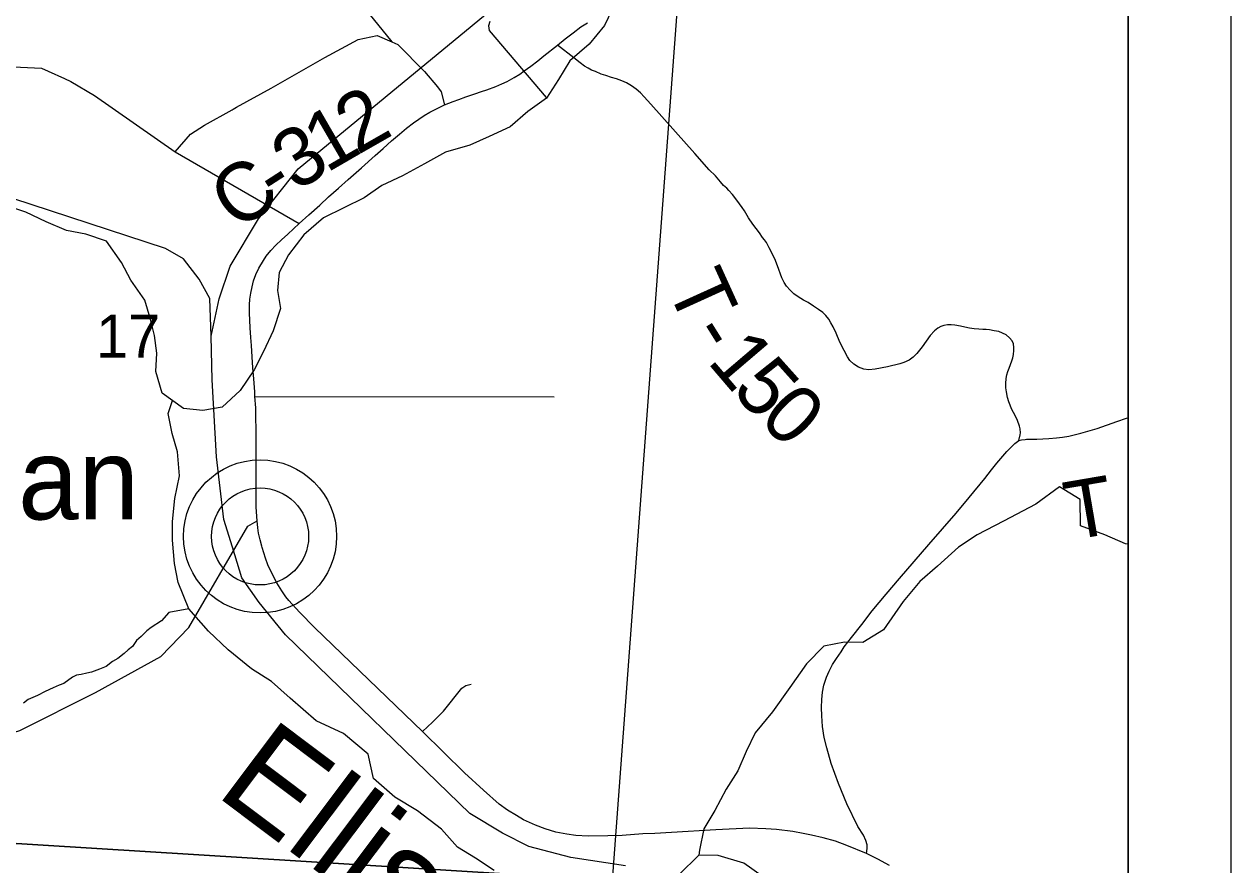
# Model space of a CAD drawing. Extents: x 0 to 34, y 0 to 22.
# Drawn here: x 7.827 to 9, y 17.328 to 18.145 of the extents above; entities that cross this region are included whole.
import ezdxf

# ---------------------------------------------------------------- set-up
doc = ezdxf.new("R2010")
doc.units = 0
for name, color, linetype in [('GM_X_County_Road', 7, 'Continuous'), ('GM_X_County_Road_Text', 7, 'Continuous'), ('GM_X_Minor_River', 7, 'Continuous'), ('GM_X_Minor_River_Text', 7, 'Continuous'), ('GM_X_Rail_Line', 7, 'Continuous'), ('GM_X_Section', 7, 'Continuous'), ('GM_X_Section_Text', 7, 'Continuous'), ('GM_X_State_Route', 7, 'Continuous'), ('GM_X_Township_Road', 7, 'Continuous'), ('GM_X_Township_Road_Text', 7, 'Continuous'), ('GM_X_Unincorporated', 7, 'Continuous'), ('GM_X_Unincorporated_Location', 7, 'Continuous'), ('GM_X_Unincorporated_Text', 7, 'Continuous'), ('SH_Cut_Line', 7, 'Continuous'), ('SH_Data', 7, 'Continuous')]:
    doc.layers.add(name, color=color, linetype=linetype)

msp = doc.modelspace()

# ---------------------------------------------------------------- linework, layer by layer
at = {"layer": 'GM_X_County_Road'}
for points in [[(8.0289, 18.0619), (8.0298, 18.0624), (8.0333, 18.0644), (8.0669, 18.0831), (8.1191, 18.1129), (8.1514, 18.1303), (8.17, 18.1341), (8.1841, 18.1279), (8.1899, 18.1254), (8.2161, 18.0993), (8.2285, 18.0843), (8.2322, 18.0794), (8.2354, 18.0667)], [(7.9734, 18.0211), (7.9886, 18.0383), (8.0022, 18.047), (8.0289, 18.0619)], [(7.6306, 17.424), (7.672, 17.4307), (7.7035, 17.4327), (7.7327, 17.4304), (7.8225, 17.4585), (7.896, 17.4953), (7.9597, 17.5306), (7.9869, 17.5587), (8.0441, 17.6573), (8.0533, 17.6625)]]:
    msp.add_lwpolyline(points, dxfattribs=at)
at = {"layer": 'GM_X_Minor_River'}
for points in [[(8.4017, 18.1663), (8.3909, 18.1439), (8.376, 18.1258), (8.3573, 18.1095), (8.3462, 18.0914), (8.3347, 18.0732), (8.3164, 18.0604), (8.2992, 18.0453), (8.2787, 18.0359), (8.2601, 18.0277), (8.2365, 18.0206), (8.216, 18.0093), (8.1946, 17.9976), (8.1745, 17.9882), (8.1573, 17.9765), (8.1178, 17.957), (8.0987, 17.9404), (8.0838, 17.9211), (8.0746, 17.9037), (8.0729, 17.8862), (8.0758, 17.8687), (8.0689, 17.8471), (8.0593, 17.8271), (8.0504, 17.8093), (8.0366, 17.7892), (8.0191, 17.773), (8.0005, 17.7696), (7.9815, 17.7716), (7.9608, 17.7866), (7.9548, 17.8075), (7.9557, 17.8253), (7.9535, 17.8424)], [(8.2794, 18.1478), (8.2782, 18.1436), (8.2789, 18.1391), (8.3342, 18.0738)], [(7.9535, 17.8424), (7.9491, 17.8595), (7.9439, 17.877), (7.9304, 17.8964), (7.9214, 17.9136), (7.9068, 17.9341), (7.8867, 17.9411), (7.8678, 17.9446), (7.8481, 17.9531), (7.8284, 17.9623), (7.811, 17.9684)], [(8.2838, 17.3224), (8.2657, 17.3343), (8.2479, 17.345), (8.2325, 17.3626), (8.2091, 17.3805), (8.1872, 17.3936), (8.1664, 17.4119), (8.1613, 17.4355), (8.1372, 17.4557), (8.1107, 17.468), (8.0854, 17.4898), (8.0673, 17.5062), (8.0477, 17.5184), (8.0251, 17.5371), (8.0059, 17.5551), (7.9867, 17.5768), (7.9766, 17.6023), (7.9729, 17.6209), (7.9708, 17.6437), (7.9709, 17.6616), (7.9733, 17.684), (7.9777, 17.706), (7.9759, 17.7295), (7.9707, 17.7474), (7.9667, 17.7668), (7.9709, 17.7792)], [(8.9, 17.6397), (8.8976, 17.6401), (8.8776, 17.6489), (8.8537, 17.6574), (8.8535, 17.6832), (8.8335, 17.6955), (8.8103, 17.6785), (8.779, 17.662), (8.7532, 17.6488), (8.7353, 17.6368), (8.7147, 17.6183), (8.6975, 17.6035), (8.6814, 17.5839), (8.6623, 17.5563), (8.6421, 17.5442), (8.6243, 17.5443), (8.6042, 17.5406), (8.5874, 17.5232), (8.5713, 17.5002), (8.5544, 17.4767), (8.5376, 17.4563), (8.5288, 17.4381), (8.5207, 17.4192), (8.5092, 17.4014), (8.4984, 17.3809), (8.4877, 17.3628), (8.4834, 17.3423), (8.4826, 17.3374)], [(7.9867, 17.5768), (7.9674, 17.5731), (7.9604, 17.5652), (7.9501, 17.5588), (7.9459, 17.5555), (7.9405, 17.5498), (7.9359, 17.5461), (7.9321, 17.5401), (7.9279, 17.5371), (7.924, 17.5333), (7.9179, 17.5285), (7.9125, 17.5255), (7.9064, 17.5206), (7.8999, 17.5181), (7.8923, 17.5151), (7.8878, 17.5144), (7.8821, 17.513), (7.8775, 17.5123), (7.8737, 17.5104), (7.8653, 17.5041), (7.8607, 17.5026), (7.855, 17.5), (7.847, 17.4963), (7.8397, 17.4926), (7.8306, 17.4885), (7.826, 17.4852)], [(8.5443, 17.3169), (8.5265, 17.3295), (8.5016, 17.3369), (8.4826, 17.3374), (8.4635, 17.3185)]]:
    msp.add_lwpolyline(points, dxfattribs=at)
at = {"layer": 'GM_X_Rail_Line'}
for points in [[(8.0084, 17.842), (8.0162, 17.8783), (8.0271, 17.9099), (8.0546, 17.9559), (8.0931, 18.0044), (8.4314, 18.2836), (8.5429, 18.3703), (8.7331, 18.5379), (8.8556, 18.668), (8.9, 18.713)], [(8.0084, 17.842), (8.0071, 17.8786), (7.997, 17.8973), (7.9816, 17.917), (7.9641, 17.927), (7.6293, 18.0366), (7.4337, 18.1028), (7.3817, 18.121), (7.3462, 18.1309), (7.3036, 18.1327), (7.2652, 18.1234), (7.2362, 18.1066), (7.1873, 18.0836), (6.9922, 17.9653), (6.9911, 17.9641), (6.4682, 17.6519)], [(8.4114, 17.3271), (8.3583, 17.3351), (8.3173, 17.3456), (8.2918, 17.3587), (8.2602, 17.3777), (8.0808, 17.5515), (8.0551, 17.5829), (8.0382, 17.607), (8.0294, 17.6367), (8.0207, 17.6635), (8.0136, 17.7246), (8.0094, 17.7994), (8.0084, 17.842)]]:
    msp.add_lwpolyline(points, dxfattribs=at)
at = {"layer": 'GM_X_Section'}
for points in [[(7.4583, 18.399), (8.4739, 18.3269), (8.3983, 17.3128), (7.3907, 17.3751)], [(7.3907, 17.3751), (8.3983, 17.3128), (8.3308, 16.3019), (7.3221, 16.3607)]]:
    msp.add_lwpolyline(points, close=True, dxfattribs=at)
at = {"layer": 'GM_X_State_Route'}
for points in [[(8.0941, 17.9514), (8.1035, 17.9597), (8.1141, 17.9693), (8.1227, 17.9772), (8.1274, 17.9814), (8.1324, 17.9859), (8.1417, 17.9942), (8.1547, 18.0056), (8.168, 18.0176), (8.1757, 18.0242), (8.1839, 18.0317), (8.1917, 18.0383), (8.1985, 18.0441), (8.2052, 18.0492), (8.2106, 18.0529), (8.2158, 18.0564), (8.2212, 18.0595), (8.2271, 18.0625), (8.2354, 18.0667), (8.2437, 18.07), (8.2492, 18.072), (8.2563, 18.0745), (8.265, 18.0775), (8.2713, 18.0797), (8.2765, 18.0814), (8.2854, 18.0846), (8.2911, 18.0871), (8.2962, 18.0895), (8.303, 18.0932), (8.3088, 18.0967), (8.3128, 18.0999), (8.3192, 18.1045), (8.3263, 18.1096), (8.332, 18.1145), (8.3452, 18.1249), (8.3529, 18.1308), (8.3604, 18.1367), (8.3679, 18.1426), (8.3746, 18.1466)], [(7.8097, 18.1042), (7.8437, 18.1024), (7.8499, 18.0996), (7.8658, 18.0924)], [(7.8658, 18.0924), (7.872, 18.0896), (7.895, 18.0757), (7.9734, 18.0211), (8.0941, 17.9514)], [(8.0533, 17.6625), (8.0523, 17.6757), (8.0522, 17.6843), (8.0524, 17.6905), (8.0523, 17.7063), (8.0523, 17.7228), (8.0523, 17.738), (8.0523, 17.7527), (8.0521, 17.7611), (8.0519, 17.7722), (8.0511, 17.7832), (8.0509, 17.7878), (8.05, 17.8004), (8.0492, 17.8112), (8.0485, 17.8218), (8.0477, 17.8327), (8.0472, 17.8405), (8.0466, 17.8499), (8.0461, 17.8573), (8.0458, 17.8642), (8.0459, 17.8724), (8.0463, 17.878), (8.0471, 17.8837), (8.0484, 17.8898), (8.0498, 17.8957), (8.0521, 17.9018), (8.055, 17.9081), (8.0593, 17.9153), (8.0621, 17.9196), (8.0666, 17.925), (8.0715, 17.9303), (8.0769, 17.9354), (8.0832, 17.9412), (8.0941, 17.9514)], [(8.0577, 17.6376), (8.0561, 17.6439), (8.0546, 17.6504), (8.0539, 17.6557), (8.0533, 17.6625)], [(8.6682, 17.3274), (8.6569, 17.3335), (8.6458, 17.3389), (8.6267, 17.3467), (8.6155, 17.3508), (8.6035, 17.3543), (8.5924, 17.3569), (8.5841, 17.3585), (8.574, 17.3603), (8.5581, 17.3622), (8.5477, 17.3629), (8.5319, 17.3636), (8.4991, 17.3619), (8.456, 17.3595), (8.44, 17.3585), (8.4284, 17.358), (8.4082, 17.3566), (8.3942, 17.356), (8.375, 17.3558), (8.3631, 17.3565), (8.3542, 17.3578), (8.3438, 17.3598), (8.3334, 17.3628), (8.3239, 17.3664), (8.3123, 17.3716), (8.3053, 17.3758), (8.2966, 17.381), (8.2885, 17.3868), (8.2732, 17.4004), (8.2548, 17.4174), (8.2141, 17.4576), (8.1094, 17.5582), (8.0943, 17.5736), (8.0839, 17.585), (8.0812, 17.5884), (8.0773, 17.5943), (8.0723, 17.602), (8.0703, 17.6058), (8.0637, 17.6196), (8.0613, 17.6261), (8.058, 17.6363), (8.0577, 17.6376)]]:
    msp.add_lwpolyline(points, dxfattribs=at)
at = {"layer": 'GM_X_Township_Road'}
for p, q in [((8.1154, 18.2136), (8.1841, 18.1279)), ((8.0511, 17.7832), (8.3419, 17.7828))]:
    msp.add_line(p, q, dxfattribs=at)
for points in [[(8.7939, 17.7404), (8.795, 17.7461), (8.7953, 17.748), (8.7951, 17.7517), (8.7944, 17.7544), (8.7927, 17.7599), (8.7902, 17.7648), (8.7871, 17.7706), (8.7841, 17.778), (8.7827, 17.7821), (8.7817, 17.7877), (8.7812, 17.7918), (8.7812, 17.796), (8.7816, 17.8006), (8.7822, 17.8042), (8.7833, 17.8075), (8.7846, 17.8108), (8.7859, 17.8143), (8.787, 17.8178), (8.788, 17.8209), (8.7886, 17.8242), (8.7891, 17.8281), (8.7891, 17.8309), (8.7886, 17.8343), (8.7873, 17.8373), (8.7848, 17.8403), (8.7816, 17.8433), (8.7781, 17.8448), (8.7745, 17.8463), (8.7697, 17.8472), (8.7654, 17.8479), (8.762, 17.8482), (8.7588, 17.8484), (8.7549, 17.8488), (8.7505, 17.8491), (8.7459, 17.8498), (8.7414, 17.8506), (8.7371, 17.8515), (8.7316, 17.8526), (8.7279, 17.853), (8.7246, 17.853), (8.7208, 17.8522), (8.7179, 17.8513), (8.7151, 17.8497), (8.7117, 17.8471), (8.7076, 17.8424), (8.7, 17.8314), (8.6947, 17.8251), (8.691, 17.8216), (8.6871, 17.8186), (8.6819, 17.8164), (8.678, 17.8151), (8.6662, 17.8122), (8.654, 17.8098), (8.6481, 17.8091), (8.6432, 17.8099), (8.638, 17.8119), (8.6333, 17.8145), (8.6296, 17.8183), (8.6274, 17.8217), (8.6239, 17.828), (8.6198, 17.8362), (8.6162, 17.8447), (8.6132, 17.8508), (8.6112, 17.8548), (8.6091, 17.8585), (8.6062, 17.8621), (8.6032, 17.8649), (8.5991, 17.8678), (8.5942, 17.871), (8.5889, 17.8747), (8.5846, 17.877), (8.5793, 17.8802), (8.575, 17.8831), (8.5716, 17.8866), (8.5681, 17.8904), (8.5657, 17.8941), (8.5635, 17.8987), (8.5591, 17.9103), (8.5565, 17.9172), (8.5511, 17.9277), (8.5486, 17.9328), (8.5467, 17.9356), (8.5446, 17.9377), (8.5417, 17.9423), (8.5353, 17.9509), (8.5311, 17.9568), (8.527, 17.9637), (8.5249, 17.967), (8.5198, 17.9741), (8.5153, 17.9797), (8.512, 17.9835), (8.5098, 17.9858), (8.5066, 17.9885), (8.5037, 17.992), (8.499, 17.9976), (8.4929, 18.0037), (8.4787, 18.0196), (8.4601, 18.0406), (8.436, 18.0673), (8.4296, 18.0746), (8.426, 18.0785), (8.4219, 18.0821), (8.4173, 18.0853), (8.4125, 18.088), (8.4077, 18.0901), (8.4026, 18.0919), (8.3977, 18.0934), (8.3924, 18.0952), (8.3879, 18.0967), (8.3822, 18.0991), (8.3785, 18.1006), (8.3752, 18.1024), (8.3714, 18.1045), (8.3673, 18.1075), (8.3611, 18.1126), (8.3452, 18.1249)], [(8.7939, 17.7404), (8.7965, 17.7411), (8.8001, 17.7415), (8.8014, 17.7416), (8.8064, 17.7416), (8.8112, 17.7416), (8.8231, 17.7424), (8.8306, 17.7429), (8.8364, 17.7436), (8.8423, 17.7448), (8.8488, 17.7464), (8.854, 17.7477), (8.8608, 17.7496), (8.87, 17.7522), (8.8891, 17.7588), (8.8986, 17.7621), (8.9, 17.7625)], [(8.7673, 17.7118), (8.7726, 17.7184), (8.7823, 17.7297), (8.7853, 17.733), (8.79, 17.7375), (8.7939, 17.7404)], [(8.6458, 17.3389), (8.6465, 17.3437), (8.6464, 17.3473), (8.6452, 17.3515), (8.6427, 17.3568), (8.6374, 17.3653), (8.6267, 17.3871), (8.6184, 17.4069), (8.6114, 17.4264), (8.607, 17.4416), (8.6046, 17.4518), (8.6031, 17.4624), (8.6022, 17.4727), (8.6021, 17.4809), (8.6023, 17.4885), (8.603, 17.4959), (8.6044, 17.5026), (8.6068, 17.5103), (8.6094, 17.5163), (8.6128, 17.5228), (8.6166, 17.5285), (8.621, 17.535), (8.6239, 17.5397), (8.6311, 17.5488), (8.6411, 17.5615), (8.6511, 17.575), (8.6648, 17.591), (8.6777, 17.6063), (8.7064, 17.6392), (8.7328, 17.6699), (8.7455, 17.6851), (8.7609, 17.7036), (8.7673, 17.7118)], [(8.2141, 17.4576), (8.2236, 17.4666), (8.2345, 17.4772), (8.2524, 17.4998), (8.256, 17.5023), (8.2613, 17.5035)]]:
    msp.add_lwpolyline(points, dxfattribs=at)
at = {"layer": 'GM_X_Township_Road_Text'}
msp.add_lwpolyline([(8.9, 17.2802), (8.9, 18.2954), (8.4739, 18.3269), (8.3983, 17.3128)], close=True, dxfattribs=at)
at = {"layer": 'GM_X_Unincorporated'}
msp.add_lwpolyline([(8.9, 14.2264), (8.9, 20.3234), (8.6245, 20.3436), (7.6038, 20.4229), (7.3955, 20.4364), (6.962, 20.4644), (6.8381, 20.4724), (6.7584, 20.4776), (6.6718, 20.4832), (6.6484, 20.4847), (4.3099, 20.6409), (3.8602, 20.6728), (3.5651, 20.6937), (3.5462, 20.4144), (3.5457, 20.4056), (3.5456, 20.4047), (3.5099, 19.8769)], dxfattribs=at)
for radius in [0.0744, 0.0472]:
    msp.add_circle((8.0561, 17.6472), radius, dxfattribs=at)
at = {"layer": 'GM_X_Unincorporated_Location'}
msp.add_line((8.0561, 17.6472), (8.0561, 17.6472), dxfattribs=at)
at = {"layer": 'SH_Cut_Line'}
msp.add_lwpolyline([(8.9, 14.1), (8.9, 20.9), (6.769, 20.9), (6.6568, 20.5136), (6.6484, 20.4847), (4.3099, 20.6409), (3.8602, 20.6728), (3.5651, 20.6937), (3.5462, 20.4144), (3.5457, 20.4056), (3.5456, 20.4047), (3.5099, 19.8769), (3.4599, 19.1361), (3.4595, 19.1305), (3.4011, 18.2653), (3.709, 17.484), (3.7367, 17.4136), (3.972, 16.8916), (4.0882, 16.6114), (4.2937, 16.1161)], dxfattribs=at)
at = {"layer": 'SH_Data'}
for p, q in [((9, 21), (9, 14)), ((8.9, 20.9), (8.9, 14.1))]:
    msp.add_line(p, q, dxfattribs=at)

# ---------------------------------------------------------------- texts
at = {"layer": 'GM_X_County_Road_Text'}
for s, rotation, p in [('2', 29.7271, (8.1506, 18.0175)), ('1', 30.1118, (8.1204, 18)), ('3', 31.4841, (8.0908, 17.9819)), ('C', 35.3335, (8.034, 17.9429)), ('-', 32.7981, (8.0715, 17.9695))]:
    msp.add_text(s, height=0.0568, rotation=rotation, dxfattribs=at).set_placement(p)
at = {"layer": 'GM_X_Minor_River_Text'}
msp.add_text('Ellisonville', height=0.094688, rotation=323.0648, dxfattribs=at).set_placement((8.0111, 17.3967))
at = {"layer": 'GM_X_Section_Text'}
msp.add_text('17', height=0.04186, rotation=0, dxfattribs=at).set_placement((7.8966, 17.821))
at = {"layer": 'GM_X_Township_Road_Text'}
for s, rotation, p in [('T', 294.4333, (8.4508, 17.8901)), ('-', 301.9874, (8.4723, 17.8442)), ('1', 310.4588, (8.49, 17.817)), ('5', 311.8019, (8.5137, 17.7893)), ('0', 315.4946, (8.5398, 17.7603)), ('T', 9.7195, (8.8438, 17.6432))]:
    msp.add_text(s, height=0.0568, rotation=rotation, dxfattribs=at).set_placement(p)
at = {"layer": 'GM_X_Unincorporated_Text'}
msp.add_text('Lisman', height=0.07898, rotation=0, dxfattribs=at).set_placement((7.5979, 17.6637))

doc.saveas('drawing.dxf')
